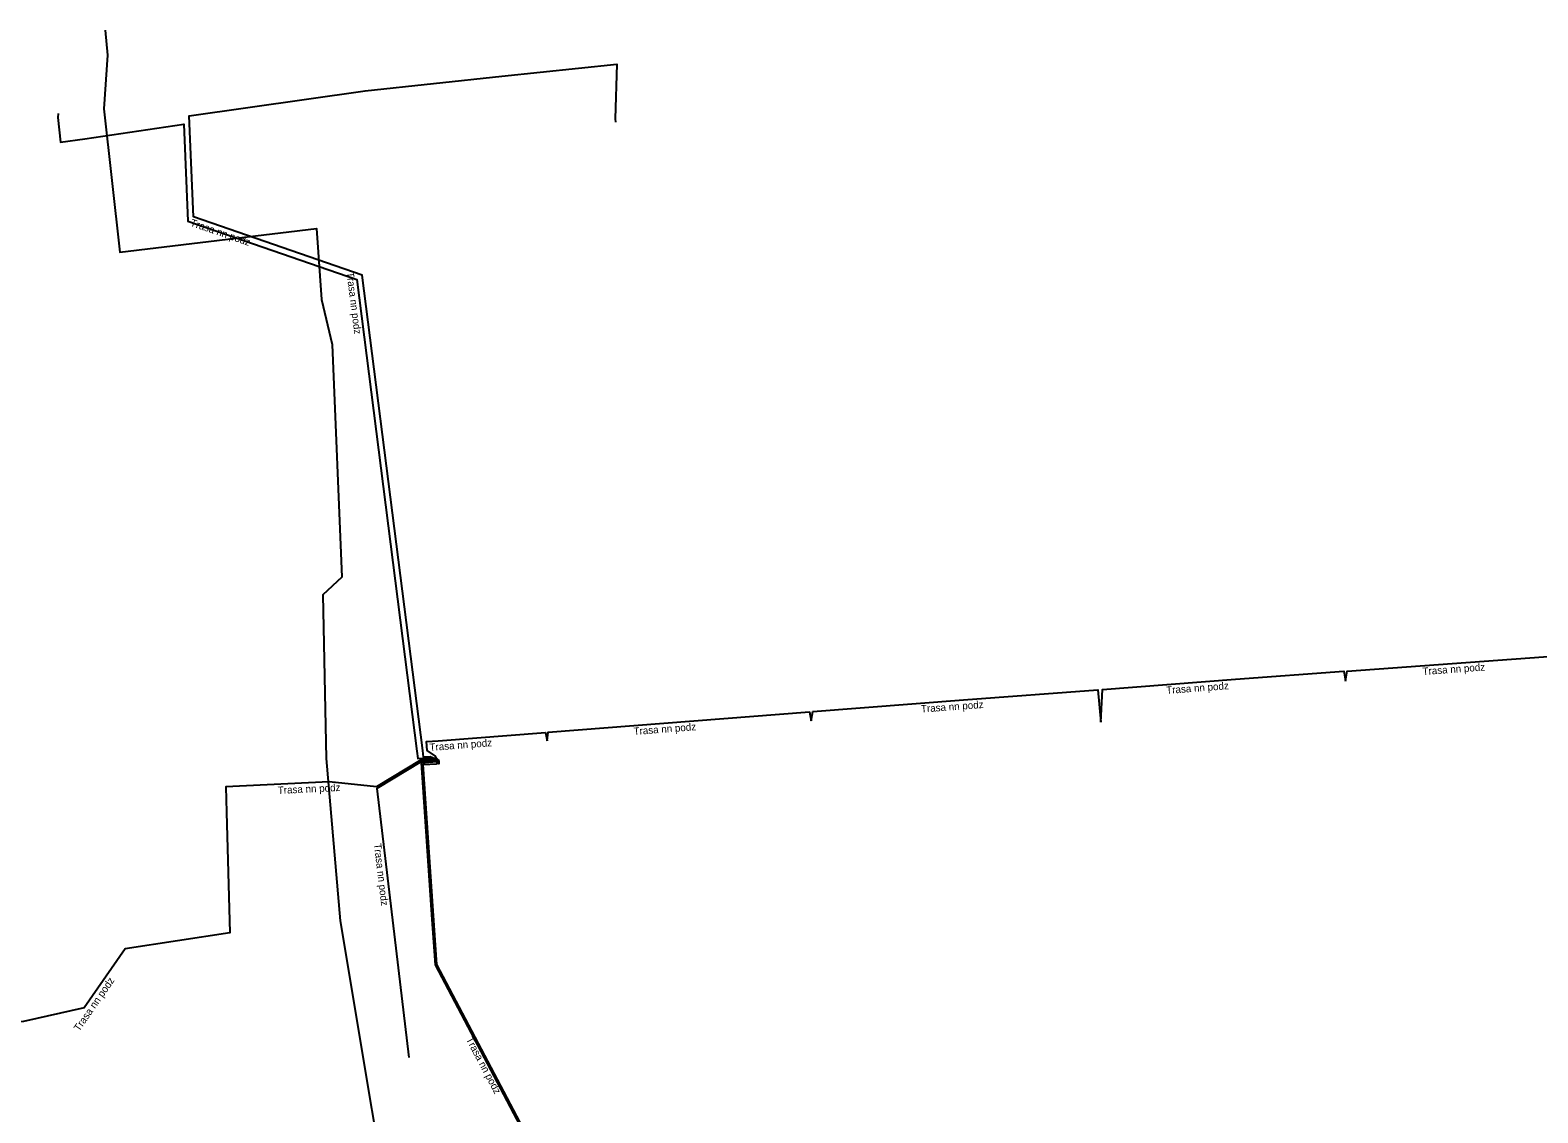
# Model space of a CAD drawing. Extents: x -873583 to -872966, y -1012951 to -1012536.
# Drawn here: x -873497.1 to -873394.3, y -1012672 to -1012598.1 of the extents above; entities that cross this region are included whole.
import ezdxf

# ---------------------------------------------------------------- set-up
doc = ezdxf.new("R2010")
doc.units = 0
for name, color, linetype in [('Popiskový text - Ostatní atributy Trasy', 7, 'Continuous'), ('Spojnice NN', 7, 'Continuous'), ('Spojnice VN', 7, 'Continuous')]:
    doc.layers.add(name, color=color, linetype=linetype)

msp = doc.modelspace()

# ---------------------------------------------------------------- linework, layer by layer
at = {"layer": 'Spojnice NN'}
for points in [[(-873469.25, -1012647.95), (-873469.84, -1012647.69), (-873470.29, -1012647.71), (-873470.34, -1012647.27), (-873474.46, -1012614.85), (-873485.96, -1012610.88), (-873486.26, -1012603.98), (-873474.27, -1012602.28), (-873464.94, -1012601.29), (-873457.12, -1012600.47), (-873457.22, -1012604.18), (-873457.2, -1012604.42)], [(-873495.2, -1012603.82), (-873495.21, -1012604.09), (-873495.03, -1012605.79), (-873493.37, -1012605.56), (-873486.63, -1012604.55), (-873486.35, -1012611.17), (-873474.83, -1012615.15), (-873470.74, -1012647.32), (-873470.67, -1012647.82), (-873469.48, -1012647.77), (-873469.25, -1012647.95)], [(-873407.44, -1012642.54), (-873407.33, -1012641.85), (-873390.83, -1012640.65), (-873390.71, -1012641.34)], [(-873424.12, -1012645.33), (-873424.01, -1012643.1), (-873414.94, -1012642.4), (-873407.55, -1012641.86), (-873407.44, -1012642.54)], [(-873443.87, -1012645.24), (-873443.76, -1012644.61), (-873433.47, -1012643.81), (-873424.33, -1012643.13), (-873424.12, -1012645.33)], [(-873461.85, -1012646.61), (-873461.78, -1012646.02), (-873443.97, -1012644.63), (-873443.87, -1012645.24)], [(-873469.25, -1012647.95), (-873469.25, -1012648.17), (-873469.48, -1012647.66), (-873470.04, -1012647.26), (-873470.08, -1012646.64), (-873469.28, -1012646.6), (-873461.98, -1012646.03), (-873461.85, -1012646.61)], [(-873469.25, -1012647.95), (-873469.48, -1012647.87), (-873470.45, -1012647.91), (-873473.49, -1012649.75), (-873476.71, -1012649.41), (-873483.76, -1012649.74), (-873483.71, -1012651.47)], [(-873469.25, -1012647.95), (-873469.53, -1012647.97), (-873470.42, -1012648.01), (-873473.46, -1012649.85), (-873471.29, -1012668.21)], [(-873427.86, -1012770.59), (-873428.26, -1012770.64), (-873429.39, -1012771.84), (-873429.99, -1012768.41), (-873430.02, -1012768.35), (-873447.58, -1012731.5), (-873448.57, -1012719.72), (-873450.03, -1012704.92), (-873456.77, -1012694.43), (-873458.35, -1012682.98), (-873469.47, -1012661.89), (-873469.69, -1012658.78), (-873470.42, -1012648.11), (-873469.41, -1012648.02), (-873469.25, -1012647.95)], [(-873450.21, -1012682.58), (-873450.32, -1012682.39), (-873456.57, -1012682.85), (-873458.26, -1012682.94), (-873469.37, -1012661.86), (-873470.31, -1012648.21), (-873469.4, -1012648.17), (-873469.25, -1012647.95)], [(-873483.71, -1012651.47), (-873483.48, -1012659.7), (-873490.62, -1012660.78), (-873493.41, -1012664.82), (-873497.56, -1012665.75), (-873506.08, -1012666.83), (-873507.16, -1012668.17), (-873506.82, -1012670.73)]]:
    msp.add_lwpolyline(points, dxfattribs=at)
at = {"layer": 'Spojnice VN'}
msp.add_lwpolyline([(-873491.98, -1012598.14), (-873491.83, -1012599.85), (-873492.09, -1012603.51), (-873490.98, -1012613.28), (-873477.58, -1012611.67), (-873477.23, -1012616.52), (-873476.51, -1012619.58), (-873475.86, -1012635.45), (-873477.15, -1012636.64), (-873476.92, -1012647.8), (-873475.98, -1012658.88), (-873471.67, -1012684.61), (-873469.16, -1012695.58), (-873464.46, -1012705.57), (-873457.94, -1012721.06), (-873455.68, -1012732.43), (-873437.43, -1012765.02)], dxfattribs=at)

# ---------------------------------------------------------------- texts
at = {"layer": 'Popiskový text - Ostatní atributy Trasy'}
for rotation, p in [(340.9329, (-873486.23, -1012611.47)), (277.237, (-873475.54, -1012614.66)), (4.1652, (-873402.17, -1012642.12)), (4.3997, (-873419.64, -1012643.41)), (4.233, (-873436.36, -1012644.68)), (4.4507, (-873455.95, -1012646.21)), (4.4384, (-873469.86, -1012647.3)), (2.7448, (-873480.21, -1012650.23)), (276.7555, (-873473.67, -1012653.63)), (55.2975, (-873493.76, -1012666.46)), (297.7911, (-873467.41, -1012666.96))]:
    msp.add_text('Trasa nn podz', height=0.5, rotation=rotation, dxfattribs=at).set_placement(p)

doc.saveas('drawing.dxf')
